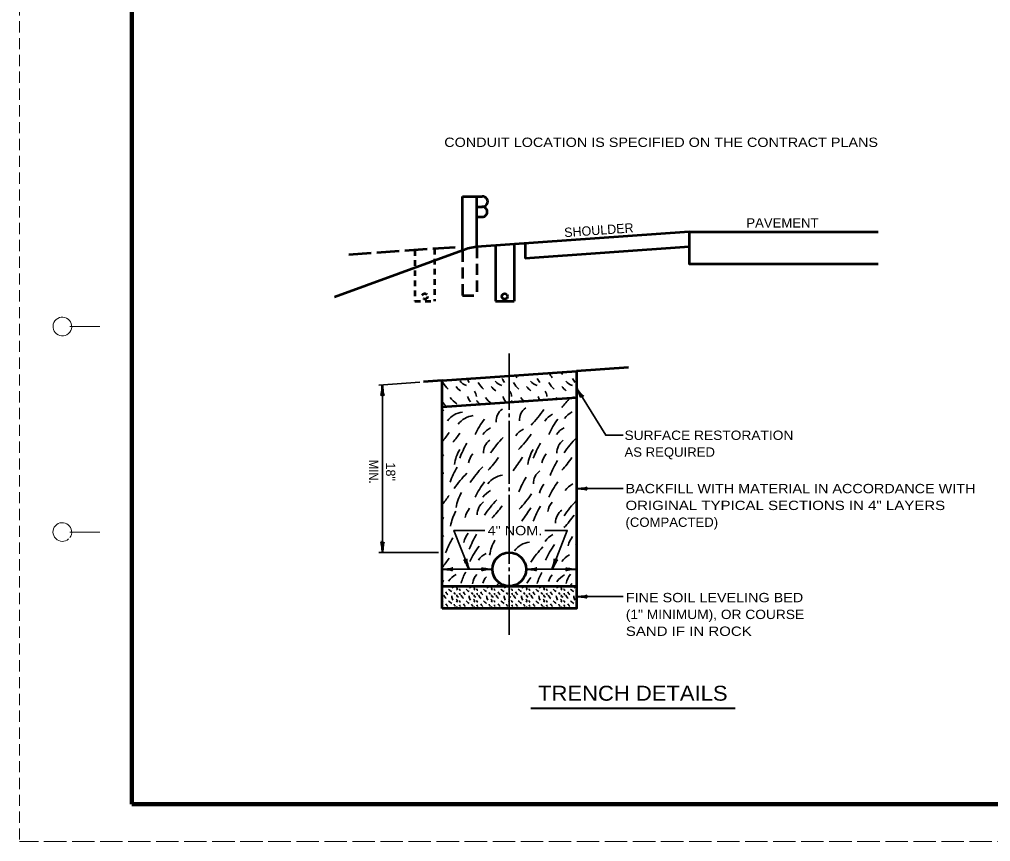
# Model space of a CAD drawing. Extents: x -1 to 679, y 0 to 440.
# Drawn here: x -1.4 to 258.3, y -0.3 to 219.8 of the extents above; entities that cross this region are included whole.
import ezdxf
from ezdxf.enums import TextEntityAlignment as Align

# ---------------------------------------------------------------- set-up
doc = ezdxf.new("R2010")
doc.units = 0
for name, pattern in [('LONG_DASHED', [7.5, 6, -1.5]), ('MEDIUM_DASHED', [4.5, 3, -1.5]), ('SHORT_DASHED', [2.7, 1.5, -1.2])]:
    doc.linetypes.add(name, pattern=pattern)
doc.layers.add('1', color=7, linetype='Continuous', lineweight=35)
doc.layers.add('61', color=7, linetype='Continuous', lineweight=35)

msp = doc.modelspace()

# ---------------------------------------------------------------- linework, layer by layer
at = {"layer": '1', "linetype": 'MEDIUM_DASHED', "lineweight": 13}
msp.add_line((-1.376, 439.785), (-1.436, -0.255), dxfattribs=at)
at = {"layer": '1', "lineweight": 53}
for p, q in [((117.092, 157.899), (117.092, 172.399)), ((117.092, 172.399), (122.342, 172.399)), ((120.842, 169.649), (122.342, 169.649)), ((120.842, 166.899), (122.342, 166.899)), ((177.703, 162.876), (228.203, 162.876)), ((125.842, 159.249), (125.842, 144.399)), ((130.842, 159.599), (130.842, 144.399)), ((133.842, 159.808), (133.842, 155.808)), ((177.703, 158.875), (133.842, 155.808)), ((117.092, 157.899), (82.793, 145.416)), ((125.842, 144.399), (130.842, 144.399)), ((111.597, 123.113), (147.51, 125.624)), ((161.476, 126.601), (147.51, 125.624)), ((147.51, 125.624), (147.51, 118.607)), ((111.597, 123.113), (106.61, 122.764)), ((111.597, 116.096), (111.597, 123.113))]:
    msp.add_line(p, q, dxfattribs=at)
at = {"layer": '1', "linetype": 'LONG_DASHED', "lineweight": 53}
msp.add_line((115.097, 158.76), (86.168, 156.737), dxfattribs=at)
at = {"layer": '1', "linetype": 'MEDIUM_DASHED', "lineweight": 53}
for p, q in [((120.842, 158.899), (120.842, 145.899)), ((117.092, 157.899), (117.092, 145.899)), ((117.092, 145.899), (120.842, 145.899))]:
    msp.add_line(p, q, dxfattribs=at)
at = {"layer": '1', "linetype": 'SHORT_DASHED', "lineweight": 53}
msp.add_line((109.592, 158.375), (109.592, 144.399), dxfattribs=at)
at = {"layer": '1'}
for p, q in [((129.554, 115.298), (129.554, 130.369)), ((105.612, 122.694), (94.639, 121.927)), ((95.639, 77.113), (95.639, 121.997)), ((129.554, 113.298), (129.554, 114.298)), ((129.554, 95.503), (129.554, 112.298)), ((129.554, 93.503), (129.554, 94.503)), ((147.51, 94.208), (160.013, 94.208)), ((129.554, 77.113), (129.554, 92.503)), ((110.597, 77.113), (94.639, 77.113)), ((129.554, 74.113), (129.554, 77.113)), ((129.554, 72.113), (129.554, 73.113)), ((125.054, 72.613), (111.597, 72.613)), ((129.554, 68.113), (129.554, 71.113)), ((134.054, 72.613), (147.51, 72.613)), ((129.554, 55.113), (129.554, 68.113)), ((147.51, 65.308), (160.013, 65.308))]:
    msp.add_line(p, q, dxfattribs=at)
at = {"layer": '1', "lineweight": 40}
msp.add_line((135.304, 35.493), (190.008, 35.493), dxfattribs=at)
at = {"layer": '1', "lineweight": 53}
for points in [[(177.703, 162.876), (120.842, 158.899), (120.842, 172.399)], [(177.703, 162.876), (177.703, 154.376), (228.203, 154.376)], [(111.597, 68.113), (111.597, 116.096), (147.51, 118.607), (147.51, 68.113)]]:
    msp.add_lwpolyline(points, dxfattribs=at)
at = {"layer": '1', "linetype": 'SHORT_DASHED', "lineweight": 53}
msp.add_lwpolyline([(104.342, 158.008), (104.342, 144.399), (109.592, 144.399)], dxfattribs=at)
at = {"layer": '1'}
for points in [[(147.51, 121.207), (155.347, 108.478), (160.013, 108.478)], [(122.997, 83.025), (114.742, 83.025), (118.789, 72.613)], [(139.046, 83.025), (145.062, 83.025), (141.016, 72.613)]]:
    msp.add_lwpolyline(points, dxfattribs=at)
at = {"layer": '1', "lineweight": 53}
msp.add_lwpolyline([(111.597, 62.113), (111.597, 68.113), (147.51, 68.113), (147.51, 62.113)], close=True, dxfattribs=at)
at = {"layer": '1', "linetype": 'SHORT_DASHED', "lineweight": 53}
msp.add_circle((106.967, 145.649), 0.75, dxfattribs=at)
at = {"layer": '1', "lineweight": 53}
for centre, radius in [((128.342, 145.649), 0.75), ((129.554, 72.613), 4.5)]:
    msp.add_circle(centre, radius, dxfattribs=at)
for centre, radius, start, end in [((122.404, 171.024), 1.376, 267.42897, 92.57103), ((122.28, 168.274), 1.376, 267.42897, 92.57103), ((121.928, 147.297), 11.653, 95.34535, 114.51748)]:
    msp.add_arc(centre, radius, start, end, dxfattribs=at)
at = {"layer": '1'}
for centre, radius, start, end in [((122.68, 110.919), 22.49, 35.21542, 39.11596), ((146.842, 129.778), 5.789, 230.36768, 239.42983), ((150.056, 127.615), 3.426, 215.86437, 221.98733), ((118.876, 126.666), 8.138, 210.01676, 226.2782), ((119.278, 125.541), 3.885, 221.18175, 253.32925), ((114.347, 120.524), 4.924, 24.88286, 38.30577), ((128.316, 126.666), 8.138, 210.01676, 226.2782), ((128.718, 125.541), 3.885, 221.18175, 253.32925), ((123.787, 120.524), 4.924, 24.88286, 39.11285), ((137.756, 126.666), 8.138, 210.01676, 226.2782), ((113.24, 110.919), 22.49, 35.21542, 37.08999), ((138.158, 125.541), 3.885, 221.18175, 253.32925), ((133.227, 120.524), 4.924, 24.88286, 39.11285), ((147.196, 126.666), 8.138, 210.01676, 226.2782), ((147.598, 125.541), 3.885, 221.18175, 253.32925), ((142.667, 120.524), 4.924, 24.88286, 39.11285), ((118.488, 123.565), 3.749, 212.31381, 237.6655), ((118.716, 118.91), 2.038, 358.18251, 41.77121), ((127.928, 123.565), 3.749, 212.31381, 237.6655), ((128.156, 118.91), 2.038, 358.18251, 41.77121), ((137.368, 123.565), 3.749, 212.31381, 237.6655), ((137.596, 118.91), 2.038, 358.18251, 41.77121), ((146.808, 123.565), 3.749, 212.31381, 237.6655), ((94.36, 103.039), 22.49, 35.71347, 39.96501), ((118.522, 121.898), 5.789, 214.79584, 239.42983), ((121.736, 119.735), 3.426, 194.9284, 222.27877), ((103.8, 103.039), 22.49, 37.70729, 41.08213), ((127.962, 121.898), 5.789, 214.79584, 237.37734), ((131.176, 119.735), 3.426, 194.9284, 222.27877), ((113.24, 103.039), 22.49, 39.74853, 41.08213), ((137.402, 121.898), 5.789, 214.79584, 227.53781), ((145.59, 115.83), 11.182, 170.36149, 171.43197), ((140.616, 119.735), 3.426, 194.9284, 211.96003), ((143.792, 116.784), 5.606, 167.85392, 168.69132), ((146.842, 121.898), 5.789, 214.79584, 219.10556), ((122.212, 135.986), 29.307, 316.85332, 323.32436), ((150.056, 119.735), 3.426, 194.9284, 200.0611), ((112.865, 109.117), 6.109, 97.86047, 101.97732), ((117.854, 108.622), 6.109, 97.86047, 142.43933), ((130.069, 112.223), 4.029, 125.55617, 183.03926), ((136.3, 112.529), 4.029, 125.55617, 183.03926), ((114.255, 131.859), 29.569, 315.74458, 326.0875), ((148.897, 109.807), 5.524, 116.78814, 145.60117), ((120.701, 107.693), 6.109, 97.86047, 142.43933), ((142.069, 98.655), 23.841, 143.51724, 155.10041), ((143.635, 109.164), 5.524, 116.78814, 145.60117), ((161.729, 98.655), 23.841, 143.51724, 155.10041), ((152.185, 109.117), 6.109, 139.93842, 142.43933), ((88.912, 125.707), 29.569, 320.10204, 326.0875), ((91.822, 125.583), 29.569, 320.10204, 326.0875), ((127.07, 105.572), 5.524, 116.78814, 145.60117), ((135.835, 105.2), 5.524, 116.78814, 145.60117), ((146.73, 105.572), 5.524, 116.78814, 145.60117), ((126.665, 103.863), 4.029, 125.55617, 183.03926), ((150.062, 86.516), 30.779, 135.94755, 145.88313), ((110.863, 125.274), 29.569, 315.74458, 326.0875), ((146.325, 103.863), 4.029, 125.55617, 183.03926), ((169.722, 86.516), 30.779, 136.19292, 145.88313), ((125.93, 99.01), 11.182, 149.50579, 171.43197), ((141.355, 92.714), 26.839, 149.42797, 158.94436), ((145.59, 99.01), 11.182, 149.50579, 171.43197), ((161.015, 92.714), 26.839, 149.42797, 158.94436), ((-16.1, 187.536), 153.36, 326.37338, 326.66613), ((124.132, 99.964), 5.606, 140.62862, 168.69132), ((102.552, 119.166), 29.307, 316.85332, 325.30832), ((4.922, 186.854), 153.36, 325.03164, 326.66613), ((143.792, 99.964), 5.606, 140.62862, 168.69132), ((165.534, 88.07), 26.839, 149.42797, 158.94436), ((122.212, 119.166), 29.307, 316.85332, 325.30832), ((138.755, 86.321), 26.839, 149.42797, 158.94436), ((144.571, 78.598), 30.779, 135.94755, 145.88313), ((140.072, 95.675), 4.029, 125.55617, 183.03926), ((112.865, 92.297), 6.109, 97.86047, 101.97732), ((140.299, 76.926), 30.779, 135.94755, 145.88313), ((128.625, 91.74), 6.109, 97.86047, 142.43933), ((157.177, 83.659), 26.839, 149.42797, 158.94436), ((152.185, 92.297), 6.109, 139.93842, 142.43933), ((142.069, 81.835), 23.841, 143.51724, 155.10041), ((127.07, 88.752), 5.524, 116.78814, 145.60117), ((143.172, 91.876), 5.606, 140.62862, 168.69132), ((161.729, 81.835), 23.841, 143.51724, 155.10041), ((149.073, 90.536), 5.524, 116.78814, 145.60117), ((88.912, 108.887), 29.569, 320.10204, 326.0875), ((126.426, 87.515), 11.182, 149.50579, 171.43197), ((148.384, 69.836), 30.779, 135.94755, 145.88313), ((110.987, 109.321), 29.569, 315.74458, 326.0875), ((169.722, 69.696), 30.779, 136.19292, 145.88313), ((123.257, 85.383), 5.606, 140.62862, 168.69132), ((125.021, 87.358), 4.029, 125.55617, 183.03926), ((103.531, 106.299), 29.307, 316.85332, 325.30832), ((7.214, 173.35), 153.36, 325.03164, 326.66613), ((161.015, 75.894), 26.839, 149.42797, 158.94436), ((145.33, 86.992), 5.606, 140.62862, 168.69132), ((145.975, 85.19), 4.029, 125.55617, 183.03926), ((-16.1, 170.716), 153.36, 326.37338, 326.66613), ((124.911, 82.479), 11.182, 149.50579, 171.43197), ((122.806, 103.815), 29.307, 316.85332, 325.30832), ((112.865, 75.477), 6.109, 97.86047, 101.97732), ((137.581, 67.401), 26.839, 149.42797, 158.94436), ((122.943, 78.702), 5.606, 140.62862, 168.69132), ((143.918, 68.332), 26.839, 149.42797, 158.94436), ((143.729, 76.971), 5.524, 116.78814, 145.60117), ((150.824, 77.808), 5.606, 140.62862, 168.69132), ((140.636, 64.63), 23.841, 143.51724, 155.10041), ((135.37, 74.747), 11.182, 149.50579, 171.43197), ((135.762, 73.849), 6.109, 97.86047, 142.43933), ((160.773, 57.274), 30.779, 136.19292, 145.88313), ((160.855, 65.05), 23.841, 143.51724, 155.10041), ((152.185, 75.477), 6.109, 139.93842, 142.43933), ((88.912, 92.067), 29.569, 320.10204, 326.0875), ((125.846, 71.932), 5.524, 116.78814, 145.60117), ((148.163, 71.547), 5.524, 116.78814, 145.60117), ((117.846, 66.297), 5.524, 116.78814, 145.60117), ((127.54, 66.175), 11.182, 149.50579, 165.79857), ((125.184, 67.663), 5.606, 140.62862, 168.69132), ((127.784, 67.068), 5.606, 140.62862, 161.39272), ((7.158, 154.689), 153.36, 325.98885, 326.66613), ((147.881, 66.051), 11.182, 149.50579, 165.79857), ((145.339, 67.563), 5.606, 140.62862, 161.39272), ((146.854, 66.173), 5.524, 116.78814, 145.60117), ((150.256, 67.725), 5.606, 140.62862, 168.69132), ((-16.1, 153.896), 153.36, 326.37338, 326.66613), ((114.182, 69.805), 2.357, 225.86486, 230.55554), ((116.601, 68.746), 2.426, 195.13344, 210.03985), ((115.103, 67.352), 0.498, 317.34474, 61.57588), ((118.842, 69.805), 2.357, 225.86486, 230.55554), ((121.261, 68.746), 2.426, 195.13344, 210.03985), ((119.763, 67.352), 0.498, 317.34474, 61.57588), ((123.502, 69.805), 2.357, 225.86486, 230.55554), ((125.921, 68.746), 2.426, 195.13344, 210.03985), ((124.423, 67.352), 0.498, 317.34474, 61.57588), ((102.552, 85.526), 29.307, 323.54678, 325.30832), ((128.162, 69.805), 2.357, 225.86486, 230.55554), ((130.581, 68.746), 2.426, 195.13344, 210.03985), ((129.083, 67.352), 0.498, 317.34474, 61.57588), ((132.822, 69.805), 2.357, 225.86486, 230.55554), ((135.241, 68.746), 2.426, 195.13344, 210.03985), ((133.743, 67.352), 0.498, 317.34474, 61.57588), ((137.482, 69.805), 2.357, 225.86486, 230.55554), ((139.901, 68.746), 2.426, 195.13344, 210.03985), ((138.403, 67.352), 0.498, 317.34474, 61.57588), ((142.142, 69.805), 2.357, 225.86486, 230.55554), ((144.561, 68.746), 2.426, 195.13344, 210.03985), ((143.063, 67.352), 0.498, 317.34474, 61.57588), ((146.802, 69.805), 2.357, 225.86486, 230.55554), ((122.212, 85.526), 29.307, 323.54678, 325.30832), ((149.221, 68.746), 2.426, 195.13344, 210.03985), ((111.812, 67.273), 0.261, 214.78265, 277.12922), ((112.092, 66.228), 0.506, 192.65873, 240.71511), ((114.182, 66.645), 2.357, 204.56614, 230.55554), ((115.352, 67.823), 3.01, 204.77096, 222.58913), ((116.187, 69.862), 3.812, 221.45311, 238.05569), ((116.601, 65.586), 2.426, 182.72927, 210.03985), ((115.442, 66.493), 0.622, 185.54013, 248.19074), ((115.984, 65.628), 0.48, 159.67517, 270.27989), ((116.472, 67.273), 0.261, 150.23947, 277.12922), ((116.752, 66.228), 0.506, 178.77007, 240.71511), ((118.842, 66.645), 2.357, 204.56614, 230.55554), ((120.012, 67.823), 3.01, 204.77096, 222.58913), ((120.847, 69.862), 3.812, 221.45311, 238.05569), ((121.261, 65.586), 2.426, 182.72927, 210.03985), ((120.102, 66.493), 0.622, 185.54013, 248.19074), ((120.644, 65.628), 0.48, 159.67517, 270.27989), ((121.132, 67.273), 0.261, 150.23947, 277.12922), ((121.412, 66.228), 0.506, 178.77007, 240.71511), ((123.502, 66.645), 2.357, 204.56614, 230.55554), ((124.672, 67.823), 3.01, 204.77096, 222.58913), ((125.507, 69.862), 3.812, 221.45311, 238.05569), ((125.921, 65.586), 2.426, 182.72927, 210.03985), ((124.762, 66.493), 0.622, 185.54013, 248.19074), ((125.304, 65.628), 0.48, 159.67517, 270.27989), ((125.792, 67.273), 0.261, 150.23947, 277.12922), ((126.072, 66.228), 0.506, 178.77007, 240.71511), ((128.162, 66.645), 2.357, 204.56614, 230.55554), ((129.332, 67.823), 3.01, 204.77096, 222.58913), ((130.167, 69.862), 3.812, 221.45311, 238.05569), ((130.581, 65.586), 2.426, 182.72927, 210.03985), ((129.422, 66.493), 0.622, 185.54013, 248.19074), ((129.964, 65.628), 0.48, 159.67517, 270.27989), ((130.452, 67.273), 0.261, 150.23947, 277.12922), ((130.732, 66.228), 0.506, 178.77007, 240.71511), ((132.822, 66.645), 2.357, 204.56614, 230.55554), ((133.992, 67.823), 3.01, 204.77096, 222.58913), ((134.827, 69.862), 3.812, 221.45311, 238.05569), ((135.241, 65.586), 2.426, 182.72927, 210.03985), ((134.082, 66.493), 0.622, 185.54013, 248.19074), ((134.624, 65.628), 0.48, 159.67517, 270.27989), ((135.112, 67.273), 0.261, 150.23947, 277.12922), ((135.392, 66.228), 0.506, 178.77007, 240.71511), ((137.482, 66.645), 2.357, 204.56614, 230.55554), ((138.652, 67.823), 3.01, 204.77096, 222.58913), ((139.487, 69.862), 3.812, 221.45311, 238.05569), ((139.901, 65.586), 2.426, 182.72927, 210.03985), ((138.742, 66.493), 0.622, 185.54013, 248.19074), ((139.284, 65.628), 0.48, 159.67517, 270.27989), ((139.772, 67.273), 0.261, 150.23947, 277.12922), ((140.052, 66.228), 0.506, 178.77007, 240.71511), ((142.142, 66.645), 2.357, 204.56614, 230.55554), ((143.312, 67.823), 3.01, 204.77096, 222.58913), ((144.147, 69.862), 3.812, 221.45311, 238.05569), ((144.561, 65.586), 2.426, 182.72927, 210.03985), ((143.402, 66.493), 0.622, 185.54013, 248.19074), ((143.944, 65.628), 0.48, 159.67517, 270.27989), ((144.432, 67.273), 0.261, 150.23947, 277.12922), ((144.712, 66.228), 0.506, 178.77007, 240.71511), ((146.802, 66.645), 2.357, 204.56614, 230.55554), ((147.972, 67.823), 3.01, 204.77096, 222.58913), ((148.807, 69.862), 3.812, 221.45311, 238.05569), ((149.221, 65.586), 2.426, 182.72927, 210.03985), ((148.062, 66.493), 0.622, 185.54013, 207.30991), ((111.812, 64.113), 0.261, 214.78265, 277.12922), ((112.092, 63.068), 0.506, 192.65873, 240.71511), ((114.182, 63.485), 2.357, 204.56614, 215.58842), ((115.352, 64.663), 3.01, 204.77096, 222.58913), ((116.187, 66.702), 3.812, 221.45311, 238.05569), ((115.442, 63.333), 0.622, 185.54013, 248.19074), ((115.103, 64.192), 0.498, 317.34474, 61.57588), ((115.984, 62.468), 0.48, 159.67517, 227.62772), ((116.472, 64.113), 0.261, 150.23947, 277.12922), ((116.752, 63.068), 0.506, 178.77007, 240.71511), ((118.842, 63.485), 2.357, 204.56614, 215.58842), ((120.012, 64.663), 3.01, 204.77096, 222.58913), ((120.847, 66.702), 3.812, 221.45311, 238.05569), ((120.102, 63.333), 0.622, 185.54013, 248.19074), ((119.763, 64.192), 0.498, 317.34474, 61.57588), ((120.644, 62.468), 0.48, 159.67517, 227.62772), ((121.132, 64.113), 0.261, 150.23947, 277.12922), ((121.412, 63.068), 0.506, 178.77007, 240.71511), ((123.502, 63.485), 2.357, 204.56614, 215.58842), ((124.672, 64.663), 3.01, 204.77096, 222.58913), ((125.507, 66.702), 3.812, 221.45311, 238.05569), ((124.762, 63.333), 0.622, 185.54013, 248.19074), ((124.423, 64.192), 0.498, 317.34474, 61.57588), ((125.304, 62.468), 0.48, 159.67517, 227.62772), ((125.792, 64.113), 0.261, 150.23947, 277.12922), ((126.072, 63.068), 0.506, 178.77007, 240.71511), ((128.162, 63.485), 2.357, 204.56614, 215.58842), ((129.332, 64.663), 3.01, 204.77096, 222.58913), ((130.167, 66.702), 3.812, 221.45311, 238.05569), ((129.422, 63.333), 0.622, 185.54013, 248.19074), ((129.083, 64.192), 0.498, 317.34474, 61.57588), ((129.964, 62.468), 0.48, 159.67517, 227.62772), ((130.452, 64.113), 0.261, 150.23947, 277.12922), ((130.732, 63.068), 0.506, 178.77007, 240.71511), ((132.822, 63.485), 2.357, 204.56614, 215.58842), ((133.992, 64.663), 3.01, 204.77096, 222.58913), ((134.827, 66.702), 3.812, 221.45311, 238.05569), ((134.082, 63.333), 0.622, 185.54013, 248.19074), ((133.743, 64.192), 0.498, 317.34474, 61.57588), ((134.624, 62.468), 0.48, 159.67517, 227.62772), ((135.112, 64.113), 0.261, 150.23947, 277.12922), ((135.392, 63.068), 0.506, 178.77007, 240.71511), ((137.482, 63.485), 2.357, 204.56614, 215.58842), ((138.652, 64.663), 3.01, 204.77096, 222.58913), ((139.487, 66.702), 3.812, 221.45311, 238.05569), ((138.742, 63.333), 0.622, 185.54013, 248.19074), ((138.403, 64.192), 0.498, 317.34474, 61.57588), ((139.284, 62.468), 0.48, 159.67517, 227.62772), ((139.772, 64.113), 0.261, 150.23947, 277.12922), ((140.052, 63.068), 0.506, 178.77007, 240.71511), ((142.142, 63.485), 2.357, 204.56614, 215.58842), ((143.312, 64.663), 3.01, 204.77096, 222.58913), ((144.147, 66.702), 3.812, 221.45311, 238.05569), ((143.402, 63.333), 0.622, 185.54013, 248.19074), ((143.063, 64.192), 0.498, 317.34474, 61.57588), ((143.944, 62.468), 0.48, 159.67517, 227.62772), ((144.432, 64.113), 0.261, 150.23947, 277.12922), ((144.712, 63.068), 0.506, 178.77007, 240.71511), ((146.802, 63.485), 2.357, 204.56614, 215.58842), ((147.972, 64.663), 3.01, 204.77096, 222.58913), ((148.807, 66.702), 3.812, 221.45311, 238.05569), ((148.062, 63.333), 0.622, 185.54013, 207.30991), ((116.601, 62.426), 2.426, 182.72927, 187.42205), ((121.261, 62.426), 2.426, 182.72927, 187.42205), ((125.921, 62.426), 2.426, 182.72927, 187.42205), ((130.581, 62.426), 2.426, 182.72927, 187.42205), ((135.241, 62.426), 2.426, 182.72927, 187.42205), ((139.901, 62.426), 2.426, 182.72927, 187.42205), ((144.561, 62.426), 2.426, 182.72927, 187.42205), ((149.221, 62.426), 2.426, 182.72927, 187.42205)]:
    msp.add_arc(centre, radius, start, end, dxfattribs=at)
at = {"layer": '1', "lineweight": 40}
for centre, major_axis, ratio, start_param, end_param in [((95.427, 120.877), (0.176, 1.756), 0.07063, 3.1407148, 5.41811), ((95.915, 120.906), (-0.156, 1.786), 0.122415, 0.8963533, 3.1415927), ((147.917, 120.142), (0.771, -1.588), 0.07063, 6.2823074, 8.5597026), ((147.917, 120.142), (0.771, -1.588), 0.07063, 6.2823074, 8.5597026), ((148.317, 120.423), (-1.069, 1.439), 0.122415, 0.8963533, 3.1415927), ((148.317, 120.423), (-1.069, 1.439), 0.122415, 0.8963533, 3.1415927), ((148.63, 93.996), (-1.756, 0.176), 0.07063, 3.1407148, 5.41811), ((148.63, 93.996), (-1.756, 0.176), 0.07063, 3.1407148, 5.41811), ((148.601, 94.484), (-1.786, -0.156), 0.122415, 0.8963533, 3.1415927), ((148.601, 94.484), (-1.786, -0.156), 0.122415, 0.8963533, 3.1415927), ((95.363, 78.204), (0.156, -1.786), 0.122415, 0.8963533, 3.1415927), ((95.851, 78.234), (-0.176, -1.756), 0.07063, 3.1407148, 5.41811), ((118.651, 73.73), (0.501, -1.721), 0.122415, 3.1415927, 5.386832), ((141.153, 73.73), (-0.501, -1.721), 0.122415, 0.8963533, 3.1415927), ((112.689, 72.889), (-1.786, -0.156), 0.122415, 0.8963533, 3.1415927), ((112.689, 72.889), (-1.786, -0.156), 0.122415, 0.8963533, 3.1415927), ((118.186, 73.581), (0.8, -1.574), 0.07063, 0.8650754, 3.1424706), ((123.933, 72.825), (1.756, -0.176), 0.07063, 3.1407148, 5.41811), ((123.933, 72.825), (1.756, -0.176), 0.07063, 3.1407148, 5.41811), ((135.145, 72.889), (-1.786, -0.156), 0.122415, 0.8963533, 3.1415927), ((135.145, 72.889), (-1.786, -0.156), 0.122415, 0.8963533, 3.1415927), ((141.619, 73.581), (-0.8, -1.574), 0.07063, 3.1407148, 5.41811), ((146.389, 72.825), (1.756, -0.176), 0.07063, 3.1407148, 5.41811), ((112.718, 72.401), (-1.756, 0.176), 0.07063, 3.1407148, 5.41811), ((112.718, 72.401), (-1.756, 0.176), 0.07063, 3.1407148, 5.41811), ((123.962, 72.337), (1.786, 0.156), 0.122415, 0.8963533, 3.1415927), ((123.962, 72.337), (1.786, 0.156), 0.122415, 0.8963533, 3.1415927), ((135.174, 72.401), (-1.756, 0.176), 0.07063, 3.1407148, 5.41811), ((135.174, 72.401), (-1.756, 0.176), 0.07063, 3.1407148, 5.41811), ((146.419, 72.337), (1.786, 0.156), 0.122415, 0.8963533, 3.1415927), ((148.63, 65.096), (-1.756, 0.176), 0.07063, 3.1407148, 5.41811), ((148.63, 65.096), (-1.756, 0.176), 0.07063, 3.1407148, 5.41811), ((148.601, 65.584), (-1.786, -0.156), 0.122415, 0.8963533, 3.1415927), ((148.601, 65.584), (-1.786, -0.156), 0.122415, 0.8963533, 3.1415927)]:
    msp.add_ellipse(centre, major_axis=major_axis, ratio=ratio, start_param=start_param, end_param=end_param, dxfattribs=at)
at = {"layer": '61', "lineweight": 13}
for p, q in [((12.044, 137.605), (20.044, 137.605)), ((12.064, 82.585), (20.044, 82.585))]:
    msp.add_line(p, q, dxfattribs=at)
at = {"layer": '61', "lineweight": 158}
msp.add_line((667.684, 9.745), (28.624, 9.765), dxfattribs=at)
at = {"layer": '61', "linetype": 'LONG_DASHED', "lineweight": 13}
msp.add_line((678.624, -0.235), (-1.436, -0.255), dxfattribs=at)
at = {"layer": '61', "lineweight": 158}
msp.add_lwpolyline([(667.664, 429.785), (28.624, 429.785), (28.624, 9.765)], dxfattribs=at)
at = {"layer": '61', "lineweight": 13}
for centre, start, end in [((10.041, 137.586), 322.67175, 321.71615), ((10.041, 82.586), 323.13009, 312.31439)]:
    msp.add_arc(centre, 2.5, start, end, dxfattribs=at)

# ---------------------------------------------------------------- texts
at = {"layer": '1'}
for s, height, width, p in [('CONDUIT LOCATION IS SPECIFIED ON THE CONTRACT PLANS', 2.5, 1.15, (112.17, 185.635)), ('PAVEMENT', 2.5, 1.05, (192.952, 164.076)), ('SURFACE RESTORATION', 2.5, 1.1, (160.372, 107.235)), ('AS REQUIRED', 2.5, 1.05, (160.372, 102.735)), ('BACKFILL WITH MATERIAL IN ACCORDANCE WITH', 2.5, 1.15, (160.641, 92.964)), ('ORIGINAL TYPICAL SECTIONS IN 4" LAYERS', 2.5, 1.2, (160.641, 88.464)), ('(COMPACTED)', 2.5, 1.05, (160.641, 83.964)), ('4" NOM.', 2.5, 1.15, (123.765, 81.732)), ('FINE SOIL LEVELING BED', 2.5, 1.15, (160.731, 63.795)), ('(1" MINIMUM), OR COURSE', 2.5, 1.1, (160.731, 59.295)), ('SAND IF IN ROCK', 2.5, 1.2, (160.731, 54.795)), ('TRENCH DETAILS', 4, 1.1, (137.262, 37.451))]:
    msp.add_text(s, height=height, dxfattribs=dict(at, width=width)).set_placement(p)
msp.add_text('SHOULDER', height=2.5, rotation=4, dxfattribs=at).set_placement((144.338, 161.482))
at = {"layer": '1', "width": 0.9}
msp.add_text('MIN.', height=2.5, rotation=270, dxfattribs=at).set_placement((92.084, 98.73), align=Align.CENTER)
at = {"layer": '1'}
msp.add_text('18"', height=2.5, rotation=270, dxfattribs=at).set_placement((96.584, 98.73), align=Align.CENTER)

doc.saveas('drawing.dxf')
